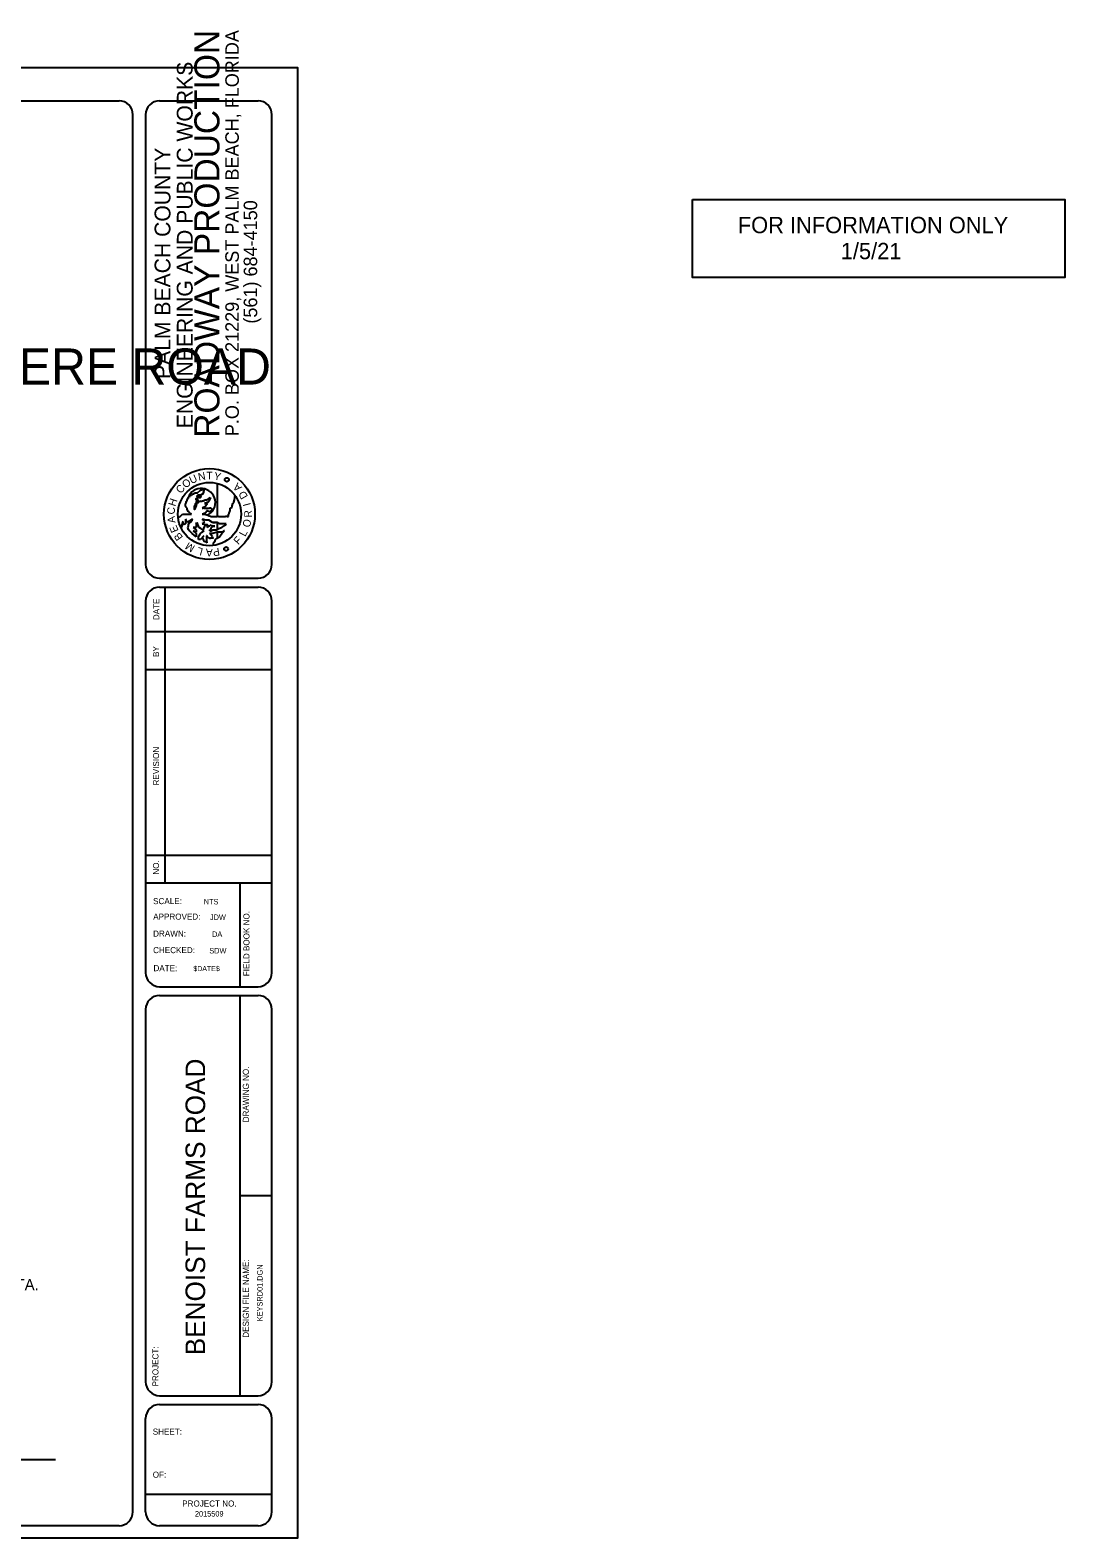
# Model space of a CAD drawing. Extents: x 801329 to 1179195, y 842463 to 1027285.
# Drawn here: x 1052425 to 1179195, y 842463 to 1027285 of the extents above; entities that cross this region are included whole.
import ezdxf

# ---------------------------------------------------------------- set-up
doc = ezdxf.new("R2010")
doc.units = 0
for name, color, linetype in [('Default', 7, 'Continuous'), ('PlotBorder_dp', 7, 'Continuous'), ('TextLabel', 7, 'Continuous')]:
    doc.layers.add(name, color=color, linetype=linetype)

msp = doc.modelspace()

# ---------------------------------------------------------------- linework, layer by layer
at = {"layer": 'Default'}
for p, q in [((813867, 1018625), (1063315, 1018625)), ((1068269, 1018625), (1080341, 1018625)), ((1065015, 845650), (1065015, 1016925)), ((1066569, 1016925), (1066569, 961794)), ((1082041, 961794), (1082041, 1016925)), ((1072181, 970293), (1072328, 970440)), ((1072328, 970440), (1072474, 970440)), ((1072474, 970440), (1072547, 970586)), ((1072547, 970586), (1072915, 970586)), ((1072915, 970586), (1073282, 970879)), ((1073282, 970879), (1073648, 971026)), ((1073574, 970440), (1073282, 970293)), ((1073648, 970586), (1073574, 970440)), ((1073648, 971026), (1073721, 970879)), ((1073721, 970879), (1073648, 970586)), ((1073648, 970586), (1073648, 970586)), ((1075335, 971613), (1075335, 967652)), ((1071448, 968972), (1071448, 969266)), ((1071448, 969266), (1071521, 969266)), ((1071521, 968825), (1071448, 968972)), ((1071521, 969413), (1071594, 969559)), ((1071521, 969266), (1071521, 969413)), ((1071667, 968679), (1071521, 968825)), ((1071594, 969559), (1071667, 969559)), ((1071667, 969706), (1071814, 969999)), ((1071667, 969559), (1071667, 969706)), ((1071667, 968532), (1071667, 968679)), ((1071814, 968239), (1071667, 968532)), ((1071814, 969999), (1071888, 969999)), ((1071814, 969999), (1071814, 969999)), ((1071961, 970146), (1071888, 969999)), ((1071961, 970146), (1072107, 970293)), ((1072107, 970293), (1072181, 970293)), ((1072621, 968972), (1072547, 968972)), ((1072547, 968972), (1072547, 968825)), ((1072547, 968825), (1072547, 968679)), ((1072547, 968825), (1072547, 968825)), ((1072547, 968532), (1072694, 968825)), ((1072547, 968679), (1072547, 968532)), ((1072621, 968972), (1072694, 969266)), ((1072768, 969266), (1072694, 969266)), ((1072768, 968972), (1072694, 968825)), ((1072842, 969853), (1072768, 969853)), ((1072768, 969853), (1072768, 969706)), ((1072768, 969706), (1072988, 969706)), ((1072842, 969559), (1072768, 969266)), ((1072768, 968972), (1072768, 969119)), ((1072988, 970293), (1072842, 970146)), ((1072842, 970146), (1073355, 970146)), ((1072988, 969999), (1072842, 969853)), ((1072988, 969559), (1072842, 969559)), ((1073061, 969413), (1072915, 969266)), ((1073061, 970293), (1072988, 970293)), ((1073282, 969999), (1072988, 969999)), ((1073061, 970293), (1073282, 970293)), ((1073282, 969559), (1073061, 969413)), ((1073282, 969999), (1073282, 969999)), ((1073282, 969559), (1073501, 969559)), ((1073648, 969559), (1073501, 969559)), ((1073721, 968825), (1073501, 968679)), ((1073501, 968679), (1073501, 968679)), ((1073501, 968679), (1073574, 968679)), ((1073501, 968679), (1073501, 968679)), ((1073721, 968679), (1073574, 968679)), ((1073648, 969559), (1073795, 969706)), ((1073941, 968972), (1073721, 968825)), ((1073721, 968679), (1074088, 968679)), ((1073795, 969706), (1074015, 969706)), ((1074235, 969413), (1073795, 969266)), ((1073795, 969266), (1074162, 969266)), ((1074162, 969266), (1073941, 968972)), ((1074015, 969706), (1074308, 969853)), ((1074088, 968679), (1074308, 968679)), ((1074308, 969559), (1074235, 969413)), ((1074308, 969853), (1074528, 969999)), ((1074381, 969706), (1074308, 969559)), ((1074308, 968679), (1074381, 968679)), ((1074528, 969999), (1074381, 969706)), ((1074602, 968679), (1074381, 968679)), ((1074602, 968679), (1074749, 968532)), ((1074895, 968532), (1074602, 968386)), ((1074749, 968532), (1074895, 968532)), ((1076949, 968679), (1077169, 968825)), ((1076949, 968532), (1076949, 968679)), ((1076949, 968386), (1076949, 968532)), ((1077169, 968972), (1077242, 969266)), ((1077169, 968825), (1077169, 968972)), ((1077242, 969266), (1077389, 969413)), ((1077389, 969413), (1077463, 969706)), ((1077463, 969706), (1077535, 970293)), ((1070568, 967505), (1070641, 967505)), ((1070641, 967505), (1070713, 967652)), ((1070713, 967652), (1070787, 967652)), ((1070787, 967652), (1070934, 967799)), ((1070934, 967799), (1071081, 967946)), ((1071081, 966919), (1071007, 966626)), ((1071007, 966626), (1071007, 966479)), ((1071081, 967946), (1071227, 967946)), ((1071153, 967065), (1071081, 966919)), ((1071153, 966919), (1071153, 967065)), ((1071153, 966626), (1071153, 966919)), ((1071448, 966772), (1071153, 966626)), ((1071153, 966626), (1071153, 966626)), ((1071153, 966626), (1071153, 966626)), ((1071227, 967946), (1071448, 967946)), ((1071448, 967946), (1071448, 967946)), ((1071448, 967946), (1071667, 967946)), ((1071521, 967211), (1071448, 967358)), ((1071448, 967358), (1071448, 967211)), ((1071448, 967211), (1071448, 967211)), ((1071448, 967211), (1071448, 966919)), ((1071448, 966919), (1071448, 966772)), ((1071667, 966919), (1071521, 967211)), ((1071667, 967946), (1071888, 967946)), ((1072328, 967358), (1071667, 966919)), ((1071888, 968239), (1071814, 968239)), ((1071814, 966626), (1071961, 966919)), ((1071814, 966479), (1071814, 966626)), ((1071961, 968092), (1071888, 968239)), ((1071888, 967946), (1072181, 967946)), ((1072181, 967946), (1071961, 968092)), ((1071961, 966919), (1072035, 966919)), ((1072035, 966919), (1072254, 967211)), ((1072254, 967211), (1072328, 967358)), ((1072768, 966772), (1072842, 966919)), ((1072768, 966772), (1072768, 966626)), ((1072768, 966626), (1072768, 966479)), ((1072915, 966772), (1072842, 966919)), ((1072842, 966919), (1072915, 966772)), ((1073061, 966479), (1072915, 966772)), ((1073574, 967946), (1073501, 967946)), ((1073574, 967946), (1073501, 967946)), ((1073501, 967946), (1073721, 967946)), ((1073941, 967211), (1073501, 967358)), ((1073501, 967358), (1073648, 967211)), ((1073648, 967211), (1073501, 967358)), ((1073795, 966919), (1073501, 966772)), ((1073501, 966772), (1074162, 966626)), ((1073574, 967946), (1073795, 968092)), ((1073721, 967065), (1073648, 967211)), ((1073721, 967946), (1073941, 967946)), ((1073721, 967065), (1073795, 966919)), ((1073721, 967065), (1073795, 966919)), ((1073867, 968092), (1073795, 968092)), ((1073941, 968239), (1073867, 968092)), ((1074088, 968239), (1073941, 968239)), ((1074308, 967211), (1073941, 967211)), ((1074381, 968239), (1074015, 968386)), ((1074015, 968386), (1074088, 968239)), ((1074162, 966626), (1074162, 966479)), ((1074749, 966919), (1074308, 967211)), ((1074602, 968386), (1074381, 968239)), ((1074381, 966479), (1074602, 966626)), ((1074528, 967652), (1075041, 967652)), ((1074602, 966626), (1074749, 966479)), ((1074749, 966919), (1075115, 966919)), ((1075115, 966919), (1074749, 966919)), ((1075041, 967652), (1075335, 967652)), ((1075335, 966919), (1075115, 966919)), ((1075482, 967652), (1075335, 967652)), ((1075629, 966772), (1075335, 966919)), ((1075335, 966919), (1075335, 966038)), ((1075482, 967652), (1075995, 967652)), ((1075995, 966772), (1075629, 966772)), ((1075995, 967652), (1076362, 967652)), ((1076435, 966772), (1075995, 966772)), ((1076069, 966479), (1076362, 966626)), ((1076582, 967652), (1076362, 967652)), ((1076362, 966626), (1076435, 966772)), ((1076582, 967652), (1076655, 967652)), ((1076655, 967652), (1076729, 967652)), ((1076729, 967946), (1076803, 968092)), ((1076729, 967652), (1076729, 967946)), ((1076803, 968092), (1076949, 968386)), ((1071007, 966479), (1070934, 966332)), ((1071741, 966332), (1071814, 966479)), ((1071814, 966038), (1071741, 966332)), ((1071741, 966332), (1071741, 966332)), ((1071888, 966038), (1071814, 966038)), ((1071961, 965891), (1071888, 966038)), ((1072107, 965745), (1071961, 965891)), ((1072254, 965598), (1072107, 965745)), ((1072768, 965159), (1072254, 965598)), ((1072768, 966332), (1072401, 966332)), ((1072401, 966332), (1072768, 966038)), ((1072768, 965745), (1072401, 965891)), ((1072401, 965891), (1072768, 965598)), ((1072768, 966479), (1072768, 966332)), ((1072768, 966332), (1072768, 966332)), ((1072768, 966038), (1072768, 965745)), ((1072768, 965598), (1072768, 965159)), ((1073135, 966332), (1073061, 966479)), ((1073061, 965305), (1073135, 965305)), ((1073061, 965305), (1073061, 965159)), ((1073061, 965011), (1073061, 965159)), ((1073061, 964865), (1073061, 965011)), ((1073135, 964865), (1073061, 964865)), ((1073061, 964865), (1073061, 964865)), ((1073355, 966185), (1073135, 966332)), ((1073135, 965305), (1073282, 965598)), ((1073282, 964865), (1073135, 964865)), ((1073282, 965598), (1073501, 965745)), ((1073282, 965598), (1073282, 965598)), ((1073721, 965305), (1073282, 964865)), ((1073501, 966038), (1073355, 966185)), ((1073574, 966038), (1073501, 966038)), ((1073501, 965745), (1073721, 965891)), ((1073721, 965891), (1073501, 965745)), ((1073721, 965891), (1073574, 966038)), ((1073574, 965011), (1073574, 965159)), ((1073648, 964865), (1073574, 965011)), ((1073721, 964718), (1073648, 964865)), ((1074088, 965305), (1074015, 965305)), ((1074015, 965305), (1074015, 965305)), ((1074015, 965305), (1074015, 965159)), ((1074015, 965159), (1074015, 965011)), ((1074015, 965011), (1074015, 964865)), ((1074015, 964865), (1074015, 964718)), ((1074162, 965159), (1074088, 965305)), ((1074162, 966332), (1074162, 966479)), ((1074162, 966332), (1074308, 966479)), ((1074162, 966332), (1074162, 966332)), ((1074162, 966332), (1074162, 966332)), ((1074308, 965011), (1074162, 965159)), ((1074381, 966479), (1074308, 966479)), ((1074381, 965011), (1074308, 965011)), ((1074821, 965598), (1074381, 965598)), ((1074455, 965598), (1074381, 965598)), ((1074381, 965011), (1074528, 965011)), ((1074602, 966185), (1074455, 966038)), ((1074455, 966038), (1074455, 966038)), ((1074455, 966038), (1074455, 965891)), ((1074455, 965891), (1074455, 966038)), ((1074455, 965891), (1074528, 965891)), ((1074749, 965159), (1074455, 965598)), ((1074528, 965891), (1074602, 965891)), ((1074602, 965011), (1074528, 965011)), ((1074675, 966332), (1074602, 966332)), ((1074602, 966185), (1074602, 966332)), ((1074602, 965891), (1074821, 966038)), ((1074749, 965011), (1074602, 965011)), ((1074821, 966479), (1074675, 966332)), ((1074749, 966479), (1074895, 966479)), ((1074749, 965159), (1074821, 965011)), ((1074895, 965011), (1074749, 965011)), ((1074821, 966479), (1075041, 966479)), ((1075041, 966479), (1074821, 966479)), ((1074821, 966038), (1075335, 966038)), ((1075335, 965745), (1074821, 965598)), ((1075041, 966479), (1074895, 966479)), ((1074895, 966479), (1075041, 966479)), ((1075041, 964571), (1075115, 964865)), ((1075115, 964865), (1075335, 965011)), ((1075556, 966185), (1075335, 966038)), ((1075922, 965745), (1075335, 965745)), ((1075335, 965745), (1075335, 965011)), ((1075335, 965011), (1075629, 965159)), ((1075556, 966185), (1075849, 966332)), ((1075629, 965159), (1075922, 965598)), ((1075849, 966332), (1075922, 966332)), ((1075922, 966332), (1075849, 966332)), ((1075922, 966332), (1076069, 966479)), ((1075922, 965598), (1076215, 965891)), ((1076141, 965891), (1075922, 965745)), ((1076215, 965891), (1076141, 965891)), ((1073795, 964571), (1073721, 964718)), ((1073867, 964571), (1073795, 964571)), ((1074015, 964571), (1073867, 964571)), ((1074015, 964718), (1074088, 964425)), ((1074015, 964571), (1074015, 964425)), ((1074088, 964425), (1074015, 964425)), ((1074895, 964425), (1075041, 964571)), ((1074895, 964278), (1074895, 964425)), ((1074895, 964278), (1074895, 964278)), ((1074895, 964131), (1074895, 964278)), ((1068269, 960094), (1080341, 960094)), ((1068269, 959006), (1080341, 959006)), ((1068904, 959006), (1068904, 922753)), ((1066569, 957306), (1066569, 911729)), ((1082041, 911729), (1082041, 957306)), ((1066569, 953559), (1082042, 953559)), ((1066569, 948890), (1082042, 948890)), ((1066569, 926147), (1082042, 926147)), ((1066533, 922753), (1082083, 922753)), ((1078123, 922753), (1078123, 910136)), ((1068269, 910029), (1080341, 910029)), ((1068269, 908941), (1080341, 908941)), ((1078123, 908941), (1078123, 859888)), ((1066569, 907241), (1066569, 861589)), ((1082041, 861589), (1082041, 907241)), ((1078123, 884415), (1082041, 884415)), ((1068269, 859889), (1080341, 859889)), ((1068270, 858800), (1080341, 858800)), ((1066570, 845650), (1066570, 857100)), ((1082041, 845650), (1082041, 857100)), ((1014202, 852087), (1055517, 852087)), ((1082083, 847781), (1066533, 847781)), ((1063315, 843950), (813867, 843950)), ((1080341, 843950), (1068270, 843950))]:
    msp.add_line(p, q, dxfattribs=at)
msp.add_lwpolyline([(1133564, 1006531), (1179195, 1006531), (1179195, 996969), (1133564, 996969)], close=True, dxfattribs=at)
for points in [[(1072915, 969266), (1072842, 969266), (1072768, 969119), (1072768, 968972), (1072694, 968825), (1072547, 968532), (1072547, 968679), (1072547, 968825), (1072547, 968825), (1072547, 968972), (1072621, 968972), (1072694, 969266), (1072768, 969266), (1072842, 969559), (1072988, 969559), (1072988, 969559), (1072988, 969706), (1072768, 969706), (1072768, 969853), (1072842, 969853), (1072988, 969999), (1073282, 969999), (1073282, 969999), (1073355, 970146), (1072842, 970146), (1072988, 970293), (1073061, 970293), (1073282, 970293), (1073574, 970440), (1073648, 970586), (1073648, 970586), (1073721, 970879), (1073648, 971026)], [(1073648, 971026), (1073721, 970879), (1073648, 970586), (1073648, 970586), (1073574, 970440), (1073282, 970293), (1073061, 970293), (1072988, 970293), (1072842, 970146), (1073355, 970146), (1073282, 969999), (1073282, 969999), (1072988, 969999), (1072842, 969853), (1072768, 969853), (1072768, 969706), (1072988, 969706), (1072988, 969559), (1072988, 969559), (1072842, 969559), (1072768, 969266), (1072694, 969266), (1072621, 968972), (1072547, 968972), (1072547, 968825), (1072547, 968825), (1072547, 968679), (1072547, 968532), (1072694, 968825), (1072768, 968972), (1072768, 969119), (1072842, 969266), (1072915, 969266)]]:
    msp.add_lwpolyline(points, dxfattribs=at)
for centre, radius in [((1074396, 967961), 5574), ((1076524, 972173), 249), ((1074396, 967961), 3876), ((1076434, 963695), 249)]:
    msp.add_circle(centre, radius, dxfattribs=at)
for centre, radius, start, end in [((1063315, 1016925), 1700, 0, 90), ((1068269, 1016925), 1700, 90, 180), ((1080341, 1016925), 1700, 0, 90), ((1073391, 969374), 1727, 296.39658, 159.2296), ((1076638, 974288), 6914, 246.84631, 252.0416), ((1074284, 966029), 652, 120.85608, 187.16512), ((1068269, 961794), 1700, 180, 270), ((1080341, 961794), 1700, 270, 360), ((1068269, 957306), 1700, 90, 180), ((1080341, 957306), 1700, 0, 90), ((1068269, 911729), 1700, 180, 270), ((1080341, 911729), 1700, 270, 360), ((1068269, 907241), 1700, 90, 180), ((1080341, 907241), 1700, 0, 90), ((1068269, 861589), 1700, 180, 270), ((1080341, 861589), 1700, 270, 360), ((1068270, 857100), 1700, 90, 180), ((1080341, 857100), 1700, 0, 90), ((1063315, 845650), 1700, 270, 360), ((1068270, 845650), 1700, 180, 270), ((1080341, 845650), 1700, 270, 360)]:
    msp.add_arc(centre, radius, start, end, dxfattribs=at)
msp.add_ellipse((1074260, 966028), major_axis=(16, 652), ratio=0.9613992, start_param=0.21389, end_param=1.7191647, dxfattribs=at)
at = {"layer": 'PlotBorder_dp'}
msp.add_lwpolyline([(801329, 842463), (1085229, 842463), (1085229, 1022663), (801329, 1022663)], close=True, dxfattribs=at)

# ---------------------------------------------------------------- texts
at = {"layer": 'Default'}
for s, height, rotation, p in [('ROADWAY PRODUCTION', 3073.81, 90, (1075619, 977315)), ('P.O. BOX 21229, WEST PALM BEACH, FLORIDA', 1653.96, 90, (1077991, 977511)), ('ENGINEERING AND PUBLIC WORKS', 1938.28, 90, (1072332, 978484)), ('PALM BEACH COUNTY', 1937.7, 90, (1069609, 984516)), ('(561) 684-4150', 1653.88, 90, (1080237, 991310)), ('O', 937, 36.82254, (1071455, 971078)), ('U', 937, 24.41588, (1072179, 971631)), ('N', 937, 11.04807, (1073089, 972042)), ('T', 937, 359.30925, (1074015, 972223)), ('Y', 937, 347.6879, (1074864, 972216)), ('C', 937, 49.28794, (1070879, 970403)), ('A', 937, 134.36794, (1078434, 971259)), ('D', 937, 119.86794, (1079141, 970125)), ('C', 937, 85.05948, (1070116, 967886)), ('H', 937, 71.25437, (1070197, 968836)), ('I', 937, 105.36794, (1079470, 969090)), ('A', 937, 97.8515, (1070241, 966919)), ('E', 937, 112.64193, (1070634, 965922)), ('O', 937, 76.36794, (1079327, 966263)), ('R', 937, 90.86794, (1079595, 967539)), ('B', 937, 125.61086, (1071195, 965119)), ('F', 937, 47.36794, (1077932, 964136)), ('L', 937, 61.86794, (1078772, 965134)), ('M', 937, 148.75881, (1072690, 964016)), ('L', 937, 164.5648, (1073676, 963742)), ('A', 937, 179.13874, (1074797, 963698)), ('P', 937, 189.79732, (1075561, 963842)), ('DATE', 742, 90, (1068249, 954959)), ('BY', 742, 90, (1068217, 950445)), ('REVISION', 742, 90, (1068217, 934696)), ('NO.', 742, 90, (1068218, 923763)), ('FIELD BOOK NO.', 742.02, 90, (1079295, 911310)), ('$DATE$', 619.5, 360, (1072423, 911938)), ('BENOIST FARMS ROAD', 2400, 90, (1073862, 864839)), ('DRAWING NO.', 742.02, 90, (1079222, 893403)), ('DESIGN FILE NAME:', 742.05, 90, (1079222, 866999)), ('KEYSRD01.DGN', 674.05, 90, (1080906, 869016)), ('PROJECT:', 742, 90, (1068145, 861024))]:
    msp.add_text(s, height=height, rotation=rotation, dxfattribs=at).set_placement(p)
for s, height, p in [('FOR INFORMATION ONLY', 2000, (1139128, 1002398)), ('1/5/21', 2000, (1151740, 999208)), ('SCALE:', 742, (1067488, 920146)), ('  NTS  ', 674, (1073190, 920110)), ('APPROVED:', 742, (1067500, 918247)), ('JDW', 674, (1074450, 918211)), ('DRAWN:', 742, (1067491, 916162)), ('DA', 674, (1074710, 916126)), ('CHECKED:', 742, (1067489, 914138)), ('SDW', 674, (1074371, 914102)), ('DATE:', 742, (1067532, 911929)), ('CONSIDERED WHEN OBTAINING SCALED DATA.', 1360, (1011136, 872825)), ('SHEET:', 742, (1067444, 855115)), ('OF: ', 742, (1067444, 849834)), ('PROJECT NO.', 742.02, (1071054, 846300)), ('2015509', 674, (1072611, 845075))]:
    msp.add_text(s, height=height, dxfattribs=at).set_placement(p)
at = {"layer": 'TextLabel'}
msp.add_text('BENOIST FARMS ROAD - SR 80 (SOUTHERN BOULEVARD) TO BELVEDERE ROAD', height=4419.99, dxfattribs=at).set_placement((850713, 983842))

doc.saveas('drawing.dxf')
